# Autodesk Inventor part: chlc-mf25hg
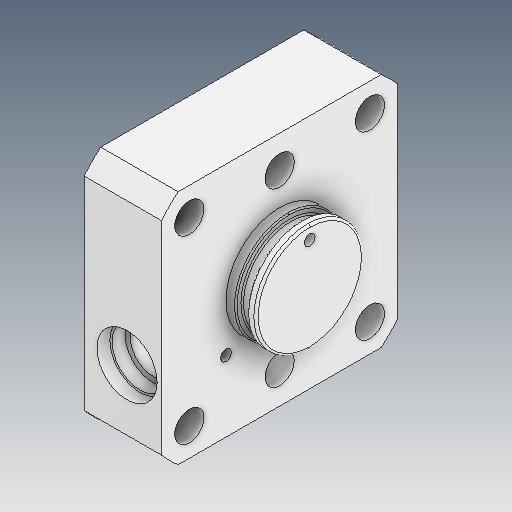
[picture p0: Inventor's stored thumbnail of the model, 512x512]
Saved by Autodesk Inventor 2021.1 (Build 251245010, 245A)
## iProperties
Created: 2021-05
Part Number: chlc-mf25hg
Material: Ogólny
Document SubType Name: Modeling
Designer: user
Density: 1 g/cm^3
Appearance: Domyślna
Author: user
Revision Number: ÈÎºÎ
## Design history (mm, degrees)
feature "ÇÐ³ý-À­Éì1"
node "Bryła1"
